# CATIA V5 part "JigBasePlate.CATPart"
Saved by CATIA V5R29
Part number: JigBasePlate
Source: Unknown
Bounding box of the stored display mesh (mm): x -110 to 110, y -60 to 60, z 0 to 10
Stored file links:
  C:\가치같이\SmartFactory_BoxErectorConveyor\Boxing(under)\JigBasePlate.CATPart
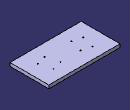
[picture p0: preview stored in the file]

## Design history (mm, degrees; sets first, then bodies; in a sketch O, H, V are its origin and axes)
Body1 (main body)
  Solid1 "PartBody": solid without history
